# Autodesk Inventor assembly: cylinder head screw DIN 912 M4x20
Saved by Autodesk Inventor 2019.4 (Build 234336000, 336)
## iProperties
Created: 2021-08
Part Number: cylinder head screw DIN 912 M4x20
Document SubType Name: Assembly
Designer: Administrator
Title: cylinder head screw DIN 912 M4x20 v4
Author: Administrator
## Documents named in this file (2)
- c:\worker\convert-fusion-r06\tmp\job-1\20\output\files\f01db8e3-9ba6-469c-91a4-18b8ab1b818d\cylinder head screw DIN 912 M4x20 v4_2.iam
- c:\worker\convert-fusion-r06\tmp\job-1\20\output\files\f01db8e3-9ba6-469c-91a4-18b8ab1b818d\HI_WUERTH 00824  20 cylinder head screw DIN 912 M4x20 8.8 BLK.ipt
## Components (1 placed, 1 different names)
1. HI_WUERTH 00824  20 cylinder head screw DIN 912 M4x20 8.8 BLK:1
